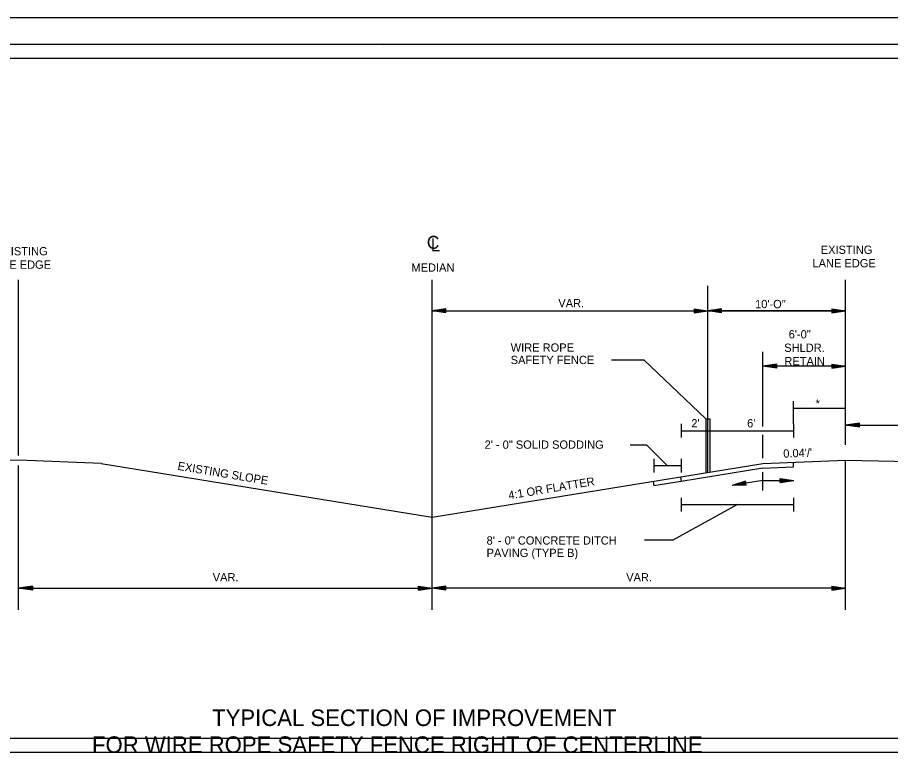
# Model space of a CAD drawing. Extents: x 1373889 to 1374222, y 382002 to 382215.
# Drawn here: x 1374000.3 to 1374127, y 382107.3 to 382215 of the extents above; entities that cross this region are included whole.
import ezdxf

# ---------------------------------------------------------------- set-up
doc = ezdxf.new("R2010")
doc.units = 0
for name, color, linetype in [('Default', 7, 'Continuous'), ('R_Border', 7, 'Continuous'), ('R_Border Plan-Plan', 7, 'Continuous'), ('R_Draft', 7, 'Continuous'), ('R_No Plot', 7, 'Continuous')]:
    doc.layers.add(name, color=color, linetype=linetype)

msp = doc.modelspace()

# ---------------------------------------------------------------- linework, layer by layer
at = {"layer": 'Default'}
for p, q in [((1374108.44, 382150.28), (1374108.45, 382150.29)), ((1374108.44, 382147.81), (1374105.97, 382147.41)), ((1374108.44, 382147.81), (1374110.94, 382147.82))]:
    msp.add_line(p, q, dxfattribs=at)
at = {"layer": 'R_Border'}
for p, q in [((1373900.91, 382211.12), (1374217.09, 382211.12)), ((1374053.43, 382210.86), (1374053.43, 382210.86)), ((1374053.43, 382210.86), (1374053.43, 382210.86))]:
    msp.add_line(p, q, dxfattribs=at)
at = {"layer": 'R_Border Plan-Plan'}
msp.add_line((1373900.91, 382108.39), (1374217.09, 382108.39), dxfattribs=at)
at = {"layer": 'R_Draft'}
for p, q in [((1374000.44, 382151.44), (1374000.44, 382176.95)), ((1374060.44, 382129.06), (1374060.44, 382176.95)), ((1374100.44, 382148.99), (1374100.44, 382176.08)), ((1374120.44, 382153), (1374120.44, 382176.95)), ((1374062.44, 382172.74), (1374060.44, 382172.44)), ((1374062.44, 382172.14), (1374060.44, 382172.44)), ((1374060.44, 382172.44), (1374120.44, 382172.44)), ((1374062.44, 382172.69), (1374060.77, 382172.44)), ((1374062.44, 382172.19), (1374060.77, 382172.44)), ((1374062.44, 382172.64), (1374061.11, 382172.44)), ((1374062.44, 382172.24), (1374061.11, 382172.44)), ((1374062.44, 382172.59), (1374061.45, 382172.44)), ((1374062.44, 382172.29), (1374061.45, 382172.44)), ((1374062.44, 382172.54), (1374061.79, 382172.44)), ((1374062.44, 382172.34), (1374061.79, 382172.44)), ((1374062.44, 382172.49), (1374062.12, 382172.44)), ((1374062.44, 382172.39), (1374062.12, 382172.44)), ((1374062.44, 382172.14), (1374062.44, 382172.74)), ((1374098.44, 382172.74), (1374100.44, 382172.44)), ((1374098.44, 382172.74), (1374098.44, 382172.14)), ((1374098.44, 382172.69), (1374100.1, 382172.44)), ((1374098.44, 382172.64), (1374099.76, 382172.44)), ((1374098.44, 382172.59), (1374099.42, 382172.44)), ((1374098.44, 382172.54), (1374099.09, 382172.44)), ((1374098.44, 382172.49), (1374098.75, 382172.44)), ((1374098.44, 382172.14), (1374100.44, 382172.44)), ((1374098.44, 382172.34), (1374099.09, 382172.44)), ((1374098.44, 382172.24), (1374099.76, 382172.44)), ((1374098.44, 382172.19), (1374100.1, 382172.44)), ((1374098.44, 382172.29), (1374099.42, 382172.44)), ((1374098.44, 382172.39), (1374098.75, 382172.44)), ((1374102.44, 382172.74), (1374100.44, 382172.44)), ((1374120.44, 382172.44), (1374100.44, 382172.44)), ((1374102.44, 382172.14), (1374100.44, 382172.44)), ((1374102.44, 382172.69), (1374100.77, 382172.44)), ((1374102.44, 382172.19), (1374100.77, 382172.44)), ((1374102.44, 382172.64), (1374101.11, 382172.44)), ((1374102.44, 382172.24), (1374101.11, 382172.44)), ((1374102.44, 382172.59), (1374101.45, 382172.44)), ((1374102.44, 382172.29), (1374101.45, 382172.44)), ((1374102.44, 382172.54), (1374101.79, 382172.44)), ((1374102.44, 382172.34), (1374101.79, 382172.44)), ((1374102.44, 382172.49), (1374102.12, 382172.44)), ((1374102.44, 382172.39), (1374102.12, 382172.44)), ((1374102.44, 382172.14), (1374102.44, 382172.74)), ((1374118.44, 382172.74), (1374120.44, 382172.44)), ((1374118.44, 382172.74), (1374118.44, 382172.14)), ((1374118.44, 382172.69), (1374120.1, 382172.44)), ((1374118.44, 382172.64), (1374119.76, 382172.44)), ((1374118.44, 382172.59), (1374119.42, 382172.44)), ((1374118.44, 382172.54), (1374119.09, 382172.44)), ((1374118.44, 382172.49), (1374118.75, 382172.44)), ((1374118.44, 382172.14), (1374120.44, 382172.44)), ((1374118.44, 382172.34), (1374119.09, 382172.44)), ((1374118.44, 382172.24), (1374119.76, 382172.44)), ((1374118.44, 382172.19), (1374120.1, 382172.44)), ((1374118.44, 382172.29), (1374119.42, 382172.44)), ((1374118.44, 382172.39), (1374118.75, 382172.44)), ((1374108.44, 382155.65), (1374108.44, 382166.48)), ((1374086.49, 382165.32), (1374091.14, 382165.32)), ((1374100.15, 382156.77), (1374091.14, 382165.32)), ((1374110.44, 382164.7), (1374108.44, 382164.4)), ((1374120.44, 382164.4), (1374108.44, 382164.4)), ((1374110.44, 382164.1), (1374108.44, 382164.4)), ((1374110.44, 382164.65), (1374108.77, 382164.4)), ((1374110.44, 382164.15), (1374108.77, 382164.4)), ((1374110.44, 382164.59), (1374109.11, 382164.4)), ((1374110.44, 382164.2), (1374109.11, 382164.4)), ((1374110.44, 382164.54), (1374109.45, 382164.4)), ((1374110.44, 382164.25), (1374109.45, 382164.4)), ((1374110.44, 382164.49), (1374109.79, 382164.4)), ((1374110.44, 382164.3), (1374109.79, 382164.4)), ((1374110.44, 382164.44), (1374110.12, 382164.4)), ((1374110.44, 382164.35), (1374110.12, 382164.4)), ((1374110.44, 382164.1), (1374110.44, 382164.7)), ((1374118.44, 382164.7), (1374120.44, 382164.4)), ((1374118.44, 382164.7), (1374118.44, 382164.1)), ((1374118.44, 382164.65), (1374120.1, 382164.4)), ((1374118.44, 382164.59), (1374119.76, 382164.4)), ((1374118.44, 382164.54), (1374119.42, 382164.4)), ((1374118.44, 382164.49), (1374119.09, 382164.4)), ((1374118.44, 382164.44), (1374118.75, 382164.4)), ((1374118.44, 382164.1), (1374120.44, 382164.4)), ((1374118.44, 382164.3), (1374119.09, 382164.4)), ((1374118.44, 382164.2), (1374119.76, 382164.4)), ((1374118.44, 382164.15), (1374120.1, 382164.4)), ((1374118.44, 382164.25), (1374119.42, 382164.4)), ((1374118.44, 382164.35), (1374118.75, 382164.4)), ((1374112.89, 382156.04), (1374112.88, 382159.33)), ((1374120.44, 382158.27), (1374112.88, 382158.27)), ((1374100.15, 382156.77), (1374100.74, 382156.77)), ((1374100.15, 382156.77), (1374100.15, 382148.98)), ((1374100.74, 382156.77), (1374100.74, 382149)), ((1374096.56, 382156.04), (1374096.56, 382154.04)), ((1374112.89, 382156.04), (1374112.89, 382154.04)), ((1374122.43, 382156.14), (1374120.43, 382155.84)), ((1374120.43, 382155.84), (1374144.41, 382155.84)), ((1374122.43, 382155.54), (1374120.43, 382155.84)), ((1374122.43, 382156.09), (1374120.76, 382155.84)), ((1374122.43, 382155.59), (1374120.76, 382155.84)), ((1374122.43, 382156.03), (1374121.1, 382155.84)), ((1374122.43, 382155.64), (1374121.1, 382155.84)), ((1374122.43, 382155.98), (1374121.44, 382155.84)), ((1374122.43, 382155.69), (1374121.44, 382155.84)), ((1374122.43, 382155.93), (1374121.78, 382155.84)), ((1374122.43, 382155.74), (1374121.78, 382155.84)), ((1374122.43, 382155.88), (1374122.11, 382155.84)), ((1374122.43, 382155.79), (1374122.11, 382155.84)), ((1374122.43, 382155.54), (1374122.43, 382156.14)), ((1374096.56, 382155.04), (1374112.89, 382155.04)), ((1374108.44, 382151.03), (1374108.44, 382154.43)), ((1374091.58, 382152.96), (1374089.19, 382152.96)), ((1374094.59, 382149.95), (1374091.58, 382152.96)), ((1374000.44, 382150.78), (1373976.12, 382150.3)), ((1374012.44, 382150.3), (1374000.44, 382150.78)), ((1374092.61, 382150.95), (1374092.61, 382148.95)), ((1374096.56, 382150.95), (1374096.56, 382148.95)), ((1374108.44, 382150.28), (1374120.44, 382150.76)), ((1374120.44, 382150.76), (1374144.41, 382150.29)), ((1374120.44, 382129.06), (1374120.44, 382150.61)), ((1374000.44, 382129.06), (1374000.44, 382149.97)), ((1374012.39, 382150.3), (1374060.44, 382142.5)), ((1374060.44, 382142.5), (1374108.44, 382150.28)), ((1374096.56, 382149.95), (1374092.61, 382149.95)), ((1374108.44, 382149.61), (1374096.56, 382147.68)), ((1374096.48, 382148.35), (1374096.56, 382147.68)), ((1374108.44, 382146.35), (1374108.44, 382149.01)), ((1374110.94, 382148.12), (1374112.94, 382147.81)), ((1374110.94, 382147.52), (1374110.94, 382148.12)), ((1374110.94, 382148.07), (1374112.6, 382147.81)), ((1374110.94, 382148.01), (1374112.26, 382147.81)), ((1374110.94, 382147.96), (1374111.93, 382147.81)), ((1374110.94, 382147.91), (1374111.59, 382147.81)), ((1374092.53, 382147.71), (1374092.61, 382147.04)), ((1374096.56, 382147.68), (1374092.61, 382147.04)), ((1374105.92, 382147.71), (1374104, 382147.09)), ((1374106.02, 382147.12), (1374104, 382147.09)), ((1374105.93, 382147.66), (1374104.33, 382147.15)), ((1374106.01, 382147.17), (1374104.33, 382147.15)), ((1374105.94, 382147.61), (1374104.67, 382147.2)), ((1374106, 382147.22), (1374104.67, 382147.2)), ((1374105.95, 382147.56), (1374104.99, 382147.26)), ((1374105.99, 382147.27), (1374104.99, 382147.26)), ((1374105.96, 382147.51), (1374105.33, 382147.31)), ((1374105.99, 382147.32), (1374105.33, 382147.31)), ((1374105.96, 382147.46), (1374105.66, 382147.36)), ((1374105.98, 382147.37), (1374105.66, 382147.36)), ((1374106.02, 382147.12), (1374105.92, 382147.71)), ((1374110.94, 382147.86), (1374111.25, 382147.81)), ((1374110.94, 382147.52), (1374112.94, 382147.81)), ((1374110.94, 382147.72), (1374111.59, 382147.81)), ((1374110.94, 382147.62), (1374112.26, 382147.81)), ((1374110.94, 382147.57), (1374112.6, 382147.81)), ((1374110.94, 382147.67), (1374111.93, 382147.81)), ((1374110.94, 382147.77), (1374111.25, 382147.81)), ((1374104.73, 382144.31), (1374095.35, 382139.15)), ((1374096.56, 382145.31), (1374096.56, 382143.31)), ((1374096.56, 382144.31), (1374112.89, 382144.31)), ((1374112.89, 382145.31), (1374112.89, 382143.31)), ((1374095.35, 382139.15), (1374091.26, 382139.15)), ((1374002.44, 382132.49), (1374000.44, 382132.19)), ((1374002.44, 382131.89), (1374000.44, 382132.19)), ((1374000.44, 382132.19), (1374060.44, 382132.19)), ((1374002.44, 382132.44), (1374000.77, 382132.19)), ((1374002.44, 382131.94), (1374000.77, 382132.19)), ((1374002.44, 382132.39), (1374001.11, 382132.19)), ((1374002.44, 382131.99), (1374001.11, 382132.19)), ((1374002.44, 382132.34), (1374001.45, 382132.19)), ((1374002.44, 382132.04), (1374001.45, 382132.19)), ((1374002.44, 382132.29), (1374001.79, 382132.19)), ((1374002.44, 382132.09), (1374001.79, 382132.19)), ((1374002.44, 382132.24), (1374002.12, 382132.19)), ((1374002.44, 382132.14), (1374002.12, 382132.19)), ((1374002.44, 382132.49), (1374002.44, 382131.89)), ((1374058.44, 382132.49), (1374060.44, 382132.19)), ((1374058.44, 382131.89), (1374058.44, 382132.49)), ((1374058.44, 382132.44), (1374060.1, 382132.19)), ((1374058.44, 382132.39), (1374059.76, 382132.19)), ((1374058.44, 382132.34), (1374059.42, 382132.19)), ((1374058.44, 382132.29), (1374059.09, 382132.19)), ((1374058.44, 382132.24), (1374058.75, 382132.19)), ((1374058.44, 382131.89), (1374060.44, 382132.19)), ((1374058.44, 382132.09), (1374059.09, 382132.19)), ((1374058.44, 382131.99), (1374059.76, 382132.19)), ((1374058.44, 382131.94), (1374060.1, 382132.19)), ((1374058.44, 382132.04), (1374059.42, 382132.19)), ((1374058.44, 382132.14), (1374058.75, 382132.19)), ((1374062.44, 382132.49), (1374060.44, 382132.19)), ((1374120.44, 382132.19), (1374060.44, 382132.19)), ((1374062.44, 382131.89), (1374060.44, 382132.19)), ((1374062.44, 382132.44), (1374060.77, 382132.19)), ((1374062.44, 382131.94), (1374060.77, 382132.19)), ((1374062.44, 382132.39), (1374061.11, 382132.19)), ((1374062.44, 382131.99), (1374061.11, 382132.19)), ((1374062.44, 382132.34), (1374061.45, 382132.19)), ((1374062.44, 382132.04), (1374061.45, 382132.19)), ((1374062.44, 382132.29), (1374061.79, 382132.19)), ((1374062.44, 382132.09), (1374061.79, 382132.19)), ((1374062.44, 382132.24), (1374062.12, 382132.19)), ((1374062.44, 382132.14), (1374062.12, 382132.19)), ((1374062.44, 382131.89), (1374062.44, 382132.49)), ((1374118.44, 382132.49), (1374120.44, 382132.19)), ((1374118.44, 382132.49), (1374118.44, 382131.89)), ((1374118.44, 382132.44), (1374120.1, 382132.19)), ((1374118.44, 382132.39), (1374119.76, 382132.19)), ((1374118.44, 382132.34), (1374119.42, 382132.19)), ((1374118.44, 382132.29), (1374119.09, 382132.19)), ((1374118.44, 382132.24), (1374118.75, 382132.19)), ((1374118.44, 382131.89), (1374120.44, 382132.19)), ((1374118.44, 382132.09), (1374119.09, 382132.19)), ((1374118.44, 382131.99), (1374119.76, 382132.19)), ((1374118.44, 382131.94), (1374120.1, 382132.19)), ((1374118.44, 382132.04), (1374119.42, 382132.19)), ((1374118.44, 382132.14), (1374118.75, 382132.19))]:
    msp.add_line(p, q, dxfattribs=at)
msp.add_lwpolyline([(1374108.44, 382149.61), (1374112.89, 382149.79), (1374112.88, 382150.46)], dxfattribs=at)
at = {"layer": 'R_No Plot'}
for points in [[(1373888.51, 382215.01), (1374221.85, 382215.01), (1374221.85, 382001.67), (1373888.51, 382001.67)], [(1374215.09, 382110.39), (1373902.91, 382110.39), (1373902.91, 382209.12), (1374152.45, 382209.12), (1374152.45, 382199.24), (1374169.99, 382199.24), (1374194.09, 382199.24), (1374194.09, 382176.9), (1374215.09, 382176.9)], [(1373902.91, 382209.12), (1374152.45, 382209.12), (1374152.45, 382199.24), (1374169.99, 382199.24), (1374194.09, 382199.24), (1374194.09, 382176.9), (1374215.09, 382176.9), (1374215.09, 382007.66), (1373902.91, 382007.66)]]:
    msp.add_lwpolyline(points, close=True, dxfattribs=at)

# ---------------------------------------------------------------- texts
at = {"layer": 'R_Draft'}
for s, height, p in [('C', 1.88, (1374059.67, 382181.43)), ('L', 1.88, (1374060.24, 382181.06)), ('EXISTING', 1.2, (1373997.16, 382180.49)), ('EXISTING', 1.2, (1374116.83, 382180.7)), ('LANE EDGE', 1.2, (1373995.96, 382178.54)), ('LANE EDGE', 1.2, (1374115.63, 382178.75)), ('MEDIAN', 1.2, (1374057.43, 382178.11)), ('VAR.', 1.2, (1374078.75, 382172.95)), ('10\'-O"', 1.2, (1374107.3, 382172.82)), ('6\'-0"', 1.2, (1374112.18, 382168.43)), ('WIRE ROPE', 1.2, (1374071.84, 382166.51)), ('SHLDR.', 1.2, (1374111.53, 382166.48)), ('SAFETY FENCE', 1.2, (1374071.84, 382164.71)), ('RETAIN', 1.2, (1374111.55, 382164.53)), ('*', 1.2, (1374116.09, 382158.4)), ("2'", 1.2, (1374098.05, 382155.52)), ("6'", 1.2, (1374106.15, 382155.52)), ('2\' - 0" SOLID SODDING', 1.2, (1374068.05, 382152.42)), ('8\' - 0" CONCRETE DITCH ', 1.2, (1374068.34, 382138.51)), ('PAVING (TYPE B)', 1.2, (1374068.34, 382136.71)), ('VAR.', 1.2, (1374028.6, 382133.17)), ('VAR.', 1.2, (1374088.6, 382133.17)), ('TYPICAL SECTION OF IMPROVEMENT', 2.4, (1374028.51, 382112.18)), ('FOR WIRE ROPE SAFETY FENCE RIGHT OF CENTERLINE', 2.4, (1374011.08, 382108.28))]:
    msp.add_text(s, height=height, dxfattribs=at).set_placement(p)
for s, rotation, p in [("0.04'/'", 2.0979, (1374111.41, 382151.12)), ('EXISTING SLOPE', 350.538, (1374023.44, 382149.37)), ('4:1 OR FLATTER', 9.462, (1374071.6, 382145.06))]:
    msp.add_text(s, height=1.2, rotation=rotation, dxfattribs=at).set_placement(p)

doc.saveas('drawing.dxf')
